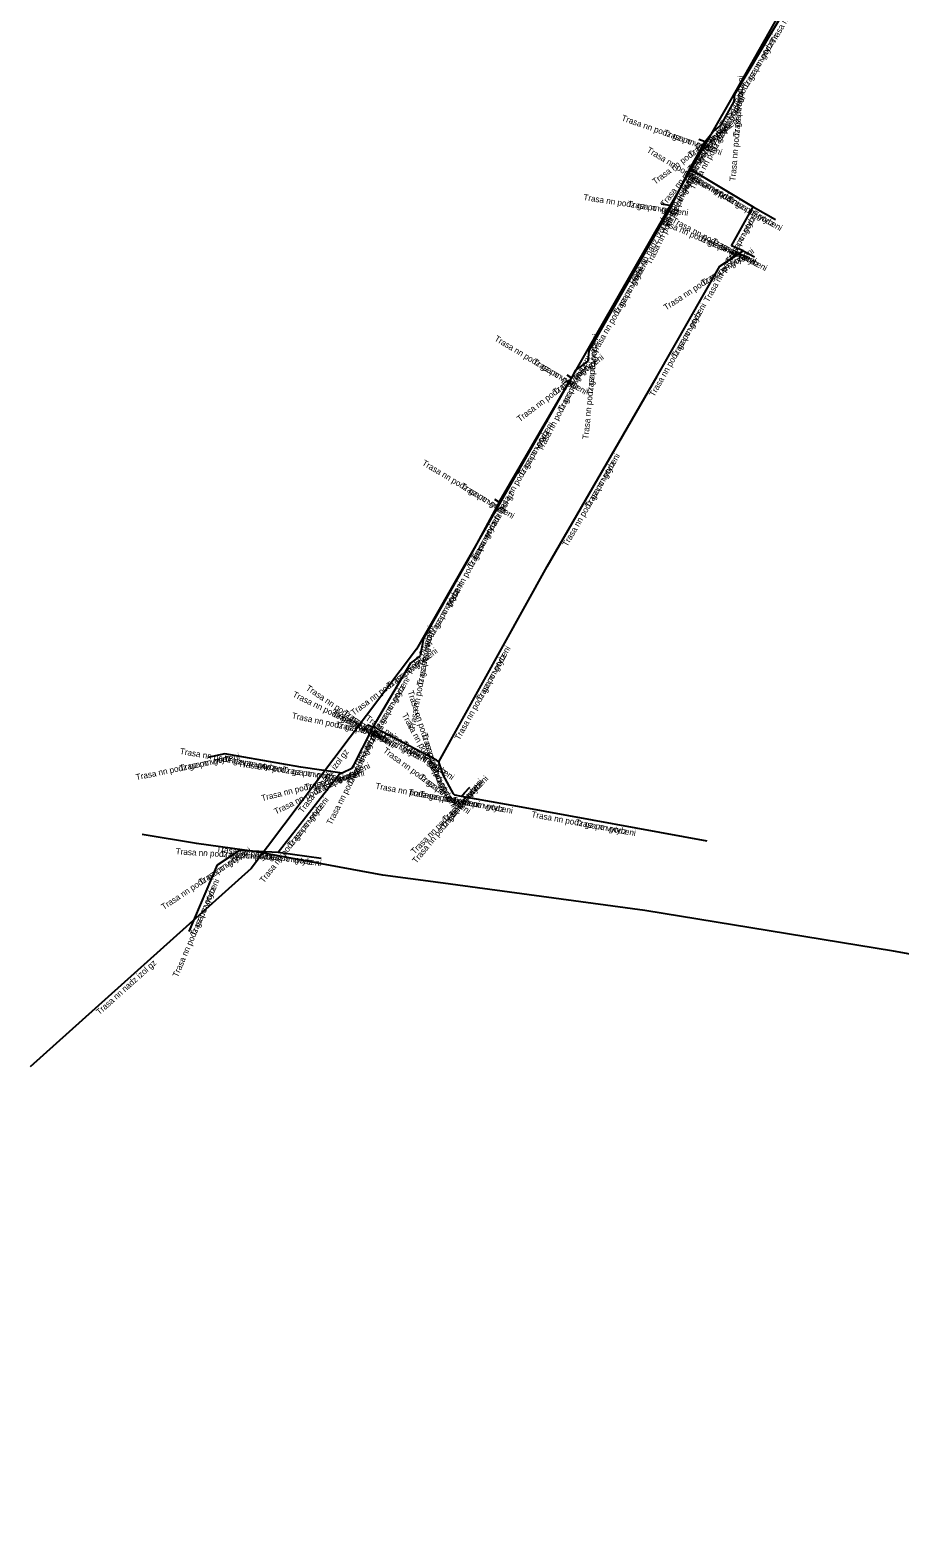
# Model space of a CAD drawing. Extents: x -600654 to -600523, y -1081832 to -1081646.
# Drawn here: x -600653.8 to -600582.4, y -1081832.4 to -1081708.6 of the extents above; entities that cross this region are included whole.
import ezdxf

# ---------------------------------------------------------------- set-up
doc = ezdxf.new("R2010")
doc.units = 0
for name, color, linetype in [('Popiskový text - Ostatní atributy Trasy', 7, 'Continuous'), ('Spojnice NN', 7, 'Continuous'), ('Spojnice VN', 7, 'Continuous')]:
    doc.layers.add(name, color=color, linetype=linetype)

msp = doc.modelspace()

# ---------------------------------------------------------------- linework, layer by layer
at = {"layer": 'Spojnice NN'}
for points in [[(-600583.71, -1081692.11), (-600596.32, -1081714.4)], [(-600595.96, -1081713.9), (-600591.83, -1081706.96)], [(-600595.96, -1081713.9), (-600591.83, -1081706.96)], [(-600596.32, -1081714.4), (-600608.34, -1081735.36)], [(-600597.1, -1081716.48), (-600596.01, -1081714.51)], [(-600597.1, -1081716.48), (-600596.01, -1081714.51)], [(-600596.01, -1081714.51), (-600595.96, -1081713.9)], [(-600596.01, -1081714.51), (-600595.96, -1081713.9)], [(-600598.38, -1081717.79), (-600597.74, -1081716.96)], [(-600598.38, -1081717.79), (-600597.74, -1081716.96)], [(-600597.74, -1081716.96), (-600597.1, -1081716.48)], [(-600597.74, -1081716.96), (-600597.1, -1081716.48)], [(-600599.65, -1081720.02), (-600598.38, -1081717.79)], [(-600599.65, -1081720.02), (-600598.38, -1081717.79)], [(-600598.92, -1081717.6), (-600598.38, -1081717.79)], [(-600598.92, -1081717.6), (-600598.38, -1081717.79)], [(-600601.14, -1081723.03), (-600599.65, -1081720.02)], [(-600601.14, -1081723.03), (-600599.65, -1081720.02)], [(-600599.65, -1081720.02), (-600594.45, -1081723.14)], [(-600599.65, -1081720.02), (-600594.45, -1081723.14)], [(-600601.14, -1081723.03), (-600607.94, -1081734.98)], [(-600601.14, -1081723.03), (-600607.94, -1081734.98)], [(-600602, -1081722.9), (-600601.14, -1081723.03)], [(-600602, -1081722.9), (-600601.14, -1081723.03)], [(-600596.24, -1081726.35), (-600594.45, -1081723.14)], [(-600596.24, -1081726.35), (-600594.45, -1081723.14)], [(-600594.45, -1081723.14), (-600592.61, -1081724.19)], [(-600594.45, -1081723.14), (-600592.61, -1081724.19)], [(-600597.19, -1081728.01), (-600595.28, -1081726.76)], [(-600597.19, -1081728.01), (-600595.28, -1081726.76)], [(-600595.28, -1081726.76), (-600596.24, -1081726.35)], [(-600595.28, -1081726.76), (-600596.24, -1081726.35)], [(-600595.28, -1081726.76), (-600594.34, -1081727.25)], [(-600595.28, -1081726.76), (-600594.34, -1081727.25)], [(-600602.34, -1081737.05), (-600597.19, -1081728.01)], [(-600602.34, -1081737.05), (-600597.19, -1081728.01)], [(-600608.34, -1081735.36), (-600622.09, -1081759.48)], [(-600607.94, -1081734.98), (-600608.02, -1081735.82)], [(-600607.94, -1081734.98), (-600608.02, -1081735.82)], [(-600609.06, -1081736.6), (-600609.36, -1081737.18)], [(-600609.06, -1081736.6), (-600609.36, -1081737.18)], [(-600608.02, -1081735.82), (-600609.06, -1081736.6)], [(-600608.02, -1081735.82), (-600609.06, -1081736.6)], [(-600615.3, -1081747.39), (-600609.36, -1081737.18)], [(-600615.3, -1081747.39), (-600609.36, -1081737.18)], [(-600611.38, -1081752.68), (-600602.34, -1081737.05)], [(-600611.38, -1081752.68), (-600602.34, -1081737.05)], [(-600609.76, -1081736.94), (-600609.36, -1081737.18)], [(-600609.76, -1081736.94), (-600609.36, -1081737.18)], [(-600615.3, -1081747.39), (-600617.9, -1081752.21)], [(-600615.3, -1081747.39), (-600617.9, -1081752.21)], [(-600615.7, -1081747.15), (-600615.3, -1081747.39)], [(-600615.7, -1081747.15), (-600615.3, -1081747.39)], [(-600617.9, -1081752.21), (-600621.53, -1081758.59)], [(-600617.9, -1081752.21), (-600621.53, -1081758.59)], [(-600620.27, -1081768.72), (-600611.38, -1081752.68)], [(-600620.27, -1081768.72), (-600611.38, -1081752.68)], [(-600621.53, -1081758.59), (-600621.79, -1081760.01)], [(-600621.53, -1081758.59), (-600621.79, -1081760.01)], [(-600622.09, -1081759.48), (-600635.67, -1081777.49)], [(-600621.79, -1081760.01), (-600622.6, -1081760.62)], [(-600621.79, -1081760.01), (-600622.6, -1081760.62)], [(-600622.6, -1081760.62), (-600625.69, -1081765.87)], [(-600622.6, -1081760.62), (-600625.69, -1081765.87)], [(-600625.69, -1081765.87), (-600627.42, -1081769.26)], [(-600625.69, -1081765.87), (-600627.42, -1081769.26)], [(-600626.12, -1081765.66), (-600625.69, -1081765.87)], [(-600626.12, -1081765.66), (-600625.69, -1081765.87)], [(-600625.4, -1081765.93), (-600625.69, -1081765.87)], [(-600625.4, -1081765.93), (-600625.69, -1081765.87)], [(-600625, -1081766.2), (-600625.4, -1081765.93)], [(-600625, -1081766.2), (-600625.4, -1081765.93)], [(-600620.47, -1081768.58), (-600625, -1081766.2)], [(-600620.47, -1081768.58), (-600625, -1081766.2)], [(-600637.84, -1081768.07), (-600639.24, -1081768.36)], [(-600637.84, -1081768.07), (-600639.24, -1081768.36)], [(-600631.6, -1081769.17), (-600637.84, -1081768.07)], [(-600631.6, -1081769.17), (-600637.84, -1081768.07)], [(-600620.27, -1081768.72), (-600620.47, -1081768.58)], [(-600620.27, -1081768.72), (-600620.47, -1081768.58)], [(-600619.92, -1081769.79), (-600620.27, -1081768.72)], [(-600619.92, -1081769.79), (-600620.27, -1081768.72)], [(-600633.46, -1081776.15), (-600628.41, -1081769.7)], [(-600633.46, -1081776.15), (-600628.41, -1081769.7)], [(-600628.21, -1081769.65), (-600631.6, -1081769.17)], [(-600628.21, -1081769.65), (-600631.6, -1081769.17)], [(-600628.41, -1081769.7), (-600628.21, -1081769.65)], [(-600628.41, -1081769.7), (-600628.21, -1081769.65)], [(-600627.42, -1081769.26), (-600628.21, -1081769.65)], [(-600627.42, -1081769.26), (-600628.21, -1081769.65)], [(-600619.07, -1081771.36), (-600619.92, -1081769.79)], [(-600619.07, -1081771.36), (-600619.92, -1081769.79)], [(-600618.92, -1081771.47), (-600619.07, -1081771.36)], [(-600618.92, -1081771.47), (-600619.07, -1081771.36)], [(-600618.41, -1081771.56), (-600618.16, -1081771.26)], [(-600618.41, -1081771.56), (-600618.16, -1081771.26)], [(-600618.16, -1081771.26), (-600617.71, -1081770.8)], [(-600618.16, -1081771.26), (-600617.71, -1081770.8)], [(-600618.41, -1081771.56), (-600618.92, -1081771.47)], [(-600618.41, -1081771.56), (-600618.92, -1081771.47)], [(-600613.48, -1081772.46), (-600618.41, -1081771.56)], [(-600613.48, -1081772.46), (-600618.41, -1081771.56)], [(-600598.23, -1081775.24), (-600613.48, -1081772.46)], [(-600598.23, -1081775.24), (-600613.48, -1081772.46)], [(-600638.44, -1081777.19), (-600636.6, -1081775.97)], [(-600638.44, -1081777.19), (-600636.6, -1081775.97)], [(-600636.6, -1081775.97), (-600633.46, -1081776.15)], [(-600636.6, -1081775.97), (-600633.46, -1081776.15)], [(-600633.46, -1081776.15), (-600629.94, -1081776.64)], [(-600633.46, -1081776.15), (-600629.94, -1081776.64)], [(-600635.67, -1081777.49), (-600653.83, -1081793.77)], [(-600640.78, -1081782.65), (-600638.44, -1081777.19)], [(-600640.78, -1081782.65), (-600638.44, -1081777.19)]]:
    msp.add_lwpolyline(points, dxfattribs=at)
at = {"layer": 'Spojnice VN'}
msp.add_lwpolyline([(-600531.73, -1081832.45), (-600531.73, -1081832.44), (-600529.68, -1081826.5), (-600523.08, -1081810.51), (-600523.1, -1081807.91), (-600524.7, -1081805.6), (-600528.64, -1081802.1), (-600535.91, -1081796.82), (-600545.03, -1081791.91), (-600551.55, -1081789.88), (-600559.69, -1081788.17), (-600571.73, -1081786.3), (-600582.93, -1081784.28), (-600603.36, -1081780.92), (-600620.33, -1081778.64), (-600624.86, -1081778.03), (-600635.23, -1081776.11), (-600640.17, -1081775.42), (-600644.62, -1081774.7)], dxfattribs=at)
msp.add_lwpolyline([(-600531.73, -1081832.45), (-600531.73, -1081832.44), (-600529.68, -1081826.5), (-600523.08, -1081810.51), (-600523.1, -1081807.91), (-600524.7, -1081805.6), (-600528.64, -1081802.1), (-600535.91, -1081796.82), (-600545.03, -1081791.91), (-600551.55, -1081789.88), (-600559.69, -1081788.17), (-600571.73, -1081786.3), (-600582.93, -1081784.28), (-600603.36, -1081780.92), (-600620.33, -1081778.64), (-600624.86, -1081778.03), (-600635.23, -1081776.11), (-600640.17, -1081775.42), (-600644.62, -1081774.7)], dxfattribs=at)

# ---------------------------------------------------------------- texts
at = {"layer": 'Popiskový text - Ostatní atributy Trasy'}
for s, rotation, p in [('Trasa nn podz gz po vytyceni', 60.6263, (-600592.69, -1081709.81)), ('Trasa nn podz gz po vytyceni', 59.2431, (-600596.83, -1081716.63)), ('Trasa nn podz', 59.2431, (-600594.95, -1081713.47)), ('Trasa nn podz gz po vytyceni', 85.3141, (-600595.9, -1081721.07)), ('Trasa nn podz', 85.3141, (-600595.59, -1081717.4)), ('Trasa nn podz gz po vytyceni', 61.0443, (-600599.29, -1081721.79)), ('Trasa nn podz gz po vytyceni', 340.6155, (-600605.31, -1081716.04)), ('Trasa nn podz gz po vytyceni', 36.8699, (-600602.5, -1081721.34)), ('Trasa nn podz', 61.0443, (-600597.51, -1081718.56)), ('Trasa nn podz gz po vytyceni', 52.3647, (-600601.72, -1081723.18)), ('Trasa nn podz', 340.6155, (-600601.84, -1081717.26)), ('Trasa nn podz', 52.3647, (-600599.47, -1081720.26)), ('Trasa nn podz', 36.8699, (-600599.55, -1081719.13)), ('Trasa nn podz gz po vytyceni', 329.0362, (-600603.24, -1081718.62)), ('Trasa nn podz gz po vytyceni', 60.3382, (-600601.83, -1081725.16)), ('Trasa nn podz', 60.3382, (-600600.01, -1081721.96)), ('Trasa nn podz gz po vytyceni', 63.6638, (-600602.84, -1081727.94)), ('Trasa nn podz', 63.6638, (-600601.21, -1081724.63)), ('Trasa nn podz', 329.0362, (-600600.08, -1081720.52)), ('Trasa nn podz gz po vytyceni', 330.2887, (-600599.79, -1081720.84)), ('Trasa nn podz gz po vytyceni', 351.4041, (-600608.42, -1081722.59)), ('Trasa nn podz', 351.4041, (-600604.78, -1081723.14)), ('Trasa nn podz', 330.2887, (-600596.59, -1081722.67)), ('Trasa nn nadz izol gz', 60.1669, (-600604.32, -1081729.66)), ('Trasa nn podz gz po vytyceni', 336.8735, (-600602.3, -1081724.47)), ('Trasa nn podz gz po vytyceni', 332.468, (-600601.17, -1081724.42)), ('Trasa nn podz gz po vytyceni', 60.8545, (-600598.11, -1081731.03)), ('Trasa nn podz', 60.8545, (-600596.31, -1081727.81)), ('Trasa nn podz', 336.8735, (-600598.91, -1081725.92)), ('Trasa nn podz gz po vytyceni', 33.2028, (-600601.6, -1081731.67)), ('Trasa nn podz', 332.468, (-600597.9, -1081726.13)), ('Trasa nn podz gz po vytyceni', 60.3585, (-600607.35, -1081735.27)), ('Trasa nn podz', 33.2028, (-600598.51, -1081729.65)), ('Trasa nn podz', 60.3585, (-600605.53, -1081732.06)), ('Trasa nn podz gz po vytyceni', 60.3303, (-600602.58, -1081738.79)), ('Trasa nn podz', 60.3303, (-600600.76, -1081735.59)), ('Trasa nn podz gz po vytyceni', 329.0362, (-600615.75, -1081734.1)), ('Trasa nn podz gz po vytyceni', 84.5597, (-600607.98, -1081742.26)), ('Trasa nn podz gz po vytyceni', 36.8699, (-600613.62, -1081740.83)), ('Trasa nn podz gz po vytyceni', 62.6501, (-600611.77, -1081743.26)), ('Trasa nn podz', 84.5597, (-600607.63, -1081738.6)), ('Trasa nn podz', 329.0362, (-600612.59, -1081736)), ('Trasa nn podz', 36.8699, (-600610.67, -1081738.62)), ('Trasa nn podz', 62.6501, (-600610.08, -1081739.98)), ('Trasa nn podz gz po vytyceni', 59.8099, (-600615.2, -1081748.52)), ('Trasa nn podz', 59.8099, (-600613.35, -1081745.33)), ('Trasa nn podz gz po vytyceni', 329.0362, (-600621.69, -1081744.31)), ('Trasa nn podz gz po vytyceni', 59.956, (-600609.72, -1081751.1)), ('Trasa nn podz', 59.956, (-600607.87, -1081747.91)), ('Trasa nn podz', 329.0362, (-600618.53, -1081746.21)), ('Trasa nn nadz izol gz', 60.314, (-600617.19, -1081752.2)), ('Trasa nn podz gz po vytyceni', 61.6567, (-600619.27, -1081756.12)), ('Trasa nn podz', 61.6567, (-600617.52, -1081752.88)), ('Trasa nn podz gz po vytyceni', 60.3616, (-600622.53, -1081761.66)), ('Trasa nn podz', 60.3616, (-600620.71, -1081758.46)), ('Trasa nn podz gz po vytyceni', 79.6242, (-600622.25, -1081766.14)), ('Trasa nn podz', 79.6242, (-600621.59, -1081762.51)), ('Trasa nn podz gz po vytyceni', 36.9829, (-600627.26, -1081764.95)), ('Trasa nn podz', 36.9829, (-600624.32, -1081762.73)), ('Trasa nn podz gz po vytyceni', 61.0031, (-600618.57, -1081766.99)), ('Trasa nn podz', 61.0031, (-600616.78, -1081763.77)), ('Trasa nn podz gz po vytyceni', 325.9806, (-600631.23, -1081762.78)), ('Trasa nn podz gz po vytyceni', 59.5201, (-600627.05, -1081769.46)), ('Trasa nn podz', 59.5201, (-600625.18, -1081766.29)), ('Trasa nn podz gz po vytyceni', 333.9704, (-600632.33, -1081763.35)), ('Trasa nn podz gz po vytyceni', 288.1131, (-600622.84, -1081762.96)), ('Trasa nn podz gz po vytyceni', 348.3106, (-600632.37, -1081765.15)), ('Trasa nn podz gz po vytyceni', 332.2832, (-600629.09, -1081764.79)), ('Trasa nn podz', 333.9704, (-600629.02, -1081764.97)), ('Trasa nn podz', 325.9806, (-600628.17, -1081764.84)), ('Trasa nn podz gz po vytyceni', 325.008, (-600626.34, -1081765.26)), ('Trasa nn podz gz po vytyceni', 298.4312, (-600623.32, -1081764.88)), ('Trasa nn podz gz po vytyceni', 62.9637, (-600629.08, -1081773.95)), ('Trasa nn podz', 348.3106, (-600628.76, -1081765.9)), ('Trasa nn podz', 332.2832, (-600625.82, -1081766.5)), ('Trasa nn podz', 288.1131, (-600621.69, -1081766.47)), ('Trasa nn podz gz po vytyceni', 350.0025, (-600641.56, -1081768.07)), ('Trasa nn nadz izol gz', 52.9828, (-600631.45, -1081772.98)), ('Trasa nn podz', 62.9637, (-600627.41, -1081770.66)), ('Trasa nn podz gz po vytyceni', 323.7462, (-600624.89, -1081767.9)), ('Trasa nn podz', 325.008, (-600623.32, -1081767.38)), ('Trasa nn podz gz po vytyceni', 11.7029, (-600645.1, -1081770.24)), ('Trasa nn podz', 11.7029, (-600641.49, -1081769.49)), ('Trasa nn podz', 350.0025, (-600637.93, -1081768.71)), ('Trasa nn podz gz po vytyceni', 351.9409, (-600636.76, -1081769.1)), ('Trasa nn podz gz po vytyceni', 26.2742, (-600633.65, -1081773.06)), ('Trasa nn podz', 298.4312, (-600621.57, -1081768.12)), ('Trasa nn podz gz po vytyceni', 14.0362, (-600634.78, -1081771.96)), ('Trasa nn podz', 351.9409, (-600633.11, -1081769.61)), ('Trasa nn podz', 14.0362, (-600631.21, -1081771.07)), ('Trasa nn podz', 26.2742, (-600630.35, -1081771.43)), ('Trasa nn podz gz po vytyceni', 45.3786, (-600622.27, -1081776.35)), ('Trasa nn podz gz po vytyceni', 50.6393, (-600622.12, -1081777.11)), ('Trasa nn podz', 323.7462, (-600621.92, -1081770.08)), ('Trasa nn podz gz po vytyceni', 349.6257, (-600625.5, -1081770.93)), ('Trasa nn podz gz po vytyceni', 349.6921, (-600622.79, -1081771.43)), ('Trasa nn podz', 349.6257, (-600621.88, -1081771.59)), ('Trasa nn podz', 50.6393, (-600619.78, -1081774.26)), ('Trasa nn podz', 45.3786, (-600619.68, -1081773.72)), ('Trasa nn podz gz po vytyceni', 51.941, (-600634.64, -1081778.71)), ('Trasa nn podz', 51.941, (-600632.36, -1081775.8)), ('Trasa nn podz', 349.6921, (-600619.16, -1081772.09)), ('Trasa nn podz gz po vytyceni', 349.6687, (-600612.69, -1081773.26)), ('Trasa nn podz', 349.6687, (-600609.07, -1081773.93)), ('Trasa nn podz gz po vytyceni', 33.5461, (-600642.86, -1081780.9)), ('Trasa nn podz gz po vytyceni', 356.7191, (-600641.89, -1081776.32)), ('Trasa nn podz', 33.5461, (-600639.78, -1081778.86)), ('Trasa nn podz gz po vytyceni', 352.0751, (-600638.56, -1081776.1)), ('Trasa nn podz', 356.7191, (-600638.21, -1081776.53)), ('Trasa nn podz', 352.0751, (-600634.91, -1081776.6)), ('Trasa nn podz gz po vytyceni', 66.8014, (-600641.7, -1081786.46)), ('Trasa nn podz', 66.8014, (-600640.25, -1081783.07)), ('Trasa nn nadz izol gz', 41.8755, (-600648.14, -1081789.54))]:
    msp.add_text(s, height=0.5, rotation=rotation, dxfattribs=at).set_placement(p)

doc.saveas('drawing.dxf')
